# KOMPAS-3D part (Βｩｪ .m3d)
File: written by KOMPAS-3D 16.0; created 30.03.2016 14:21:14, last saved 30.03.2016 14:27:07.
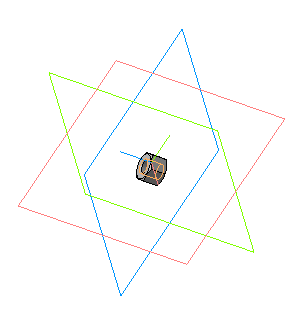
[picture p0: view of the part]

Referenced files in E:\Libs\PartLib\DATA\vault\Methods\Kompas\3D\: PLib_Nut_OST92_900.m3d
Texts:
  Гайка М4-6H ГОСТ 15523-70
  bcut1
  hole1
  hcut1
  hole2
  cut1
  (-) Гайка М4-6H ГОСТ 15523-70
